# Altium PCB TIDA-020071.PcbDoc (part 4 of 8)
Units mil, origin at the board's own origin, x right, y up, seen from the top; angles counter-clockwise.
Board outline 5750 x 4050 mil, 6 copper layers (Top Layer, GND PLANE-1, SIGNAL LAYER, SIGNAL/POWER LAYER, GND PLANE-2, Bottom Layer), stack 59.616 mil thick; 776 components, 498 nets, 2205 pads, 871 vias.
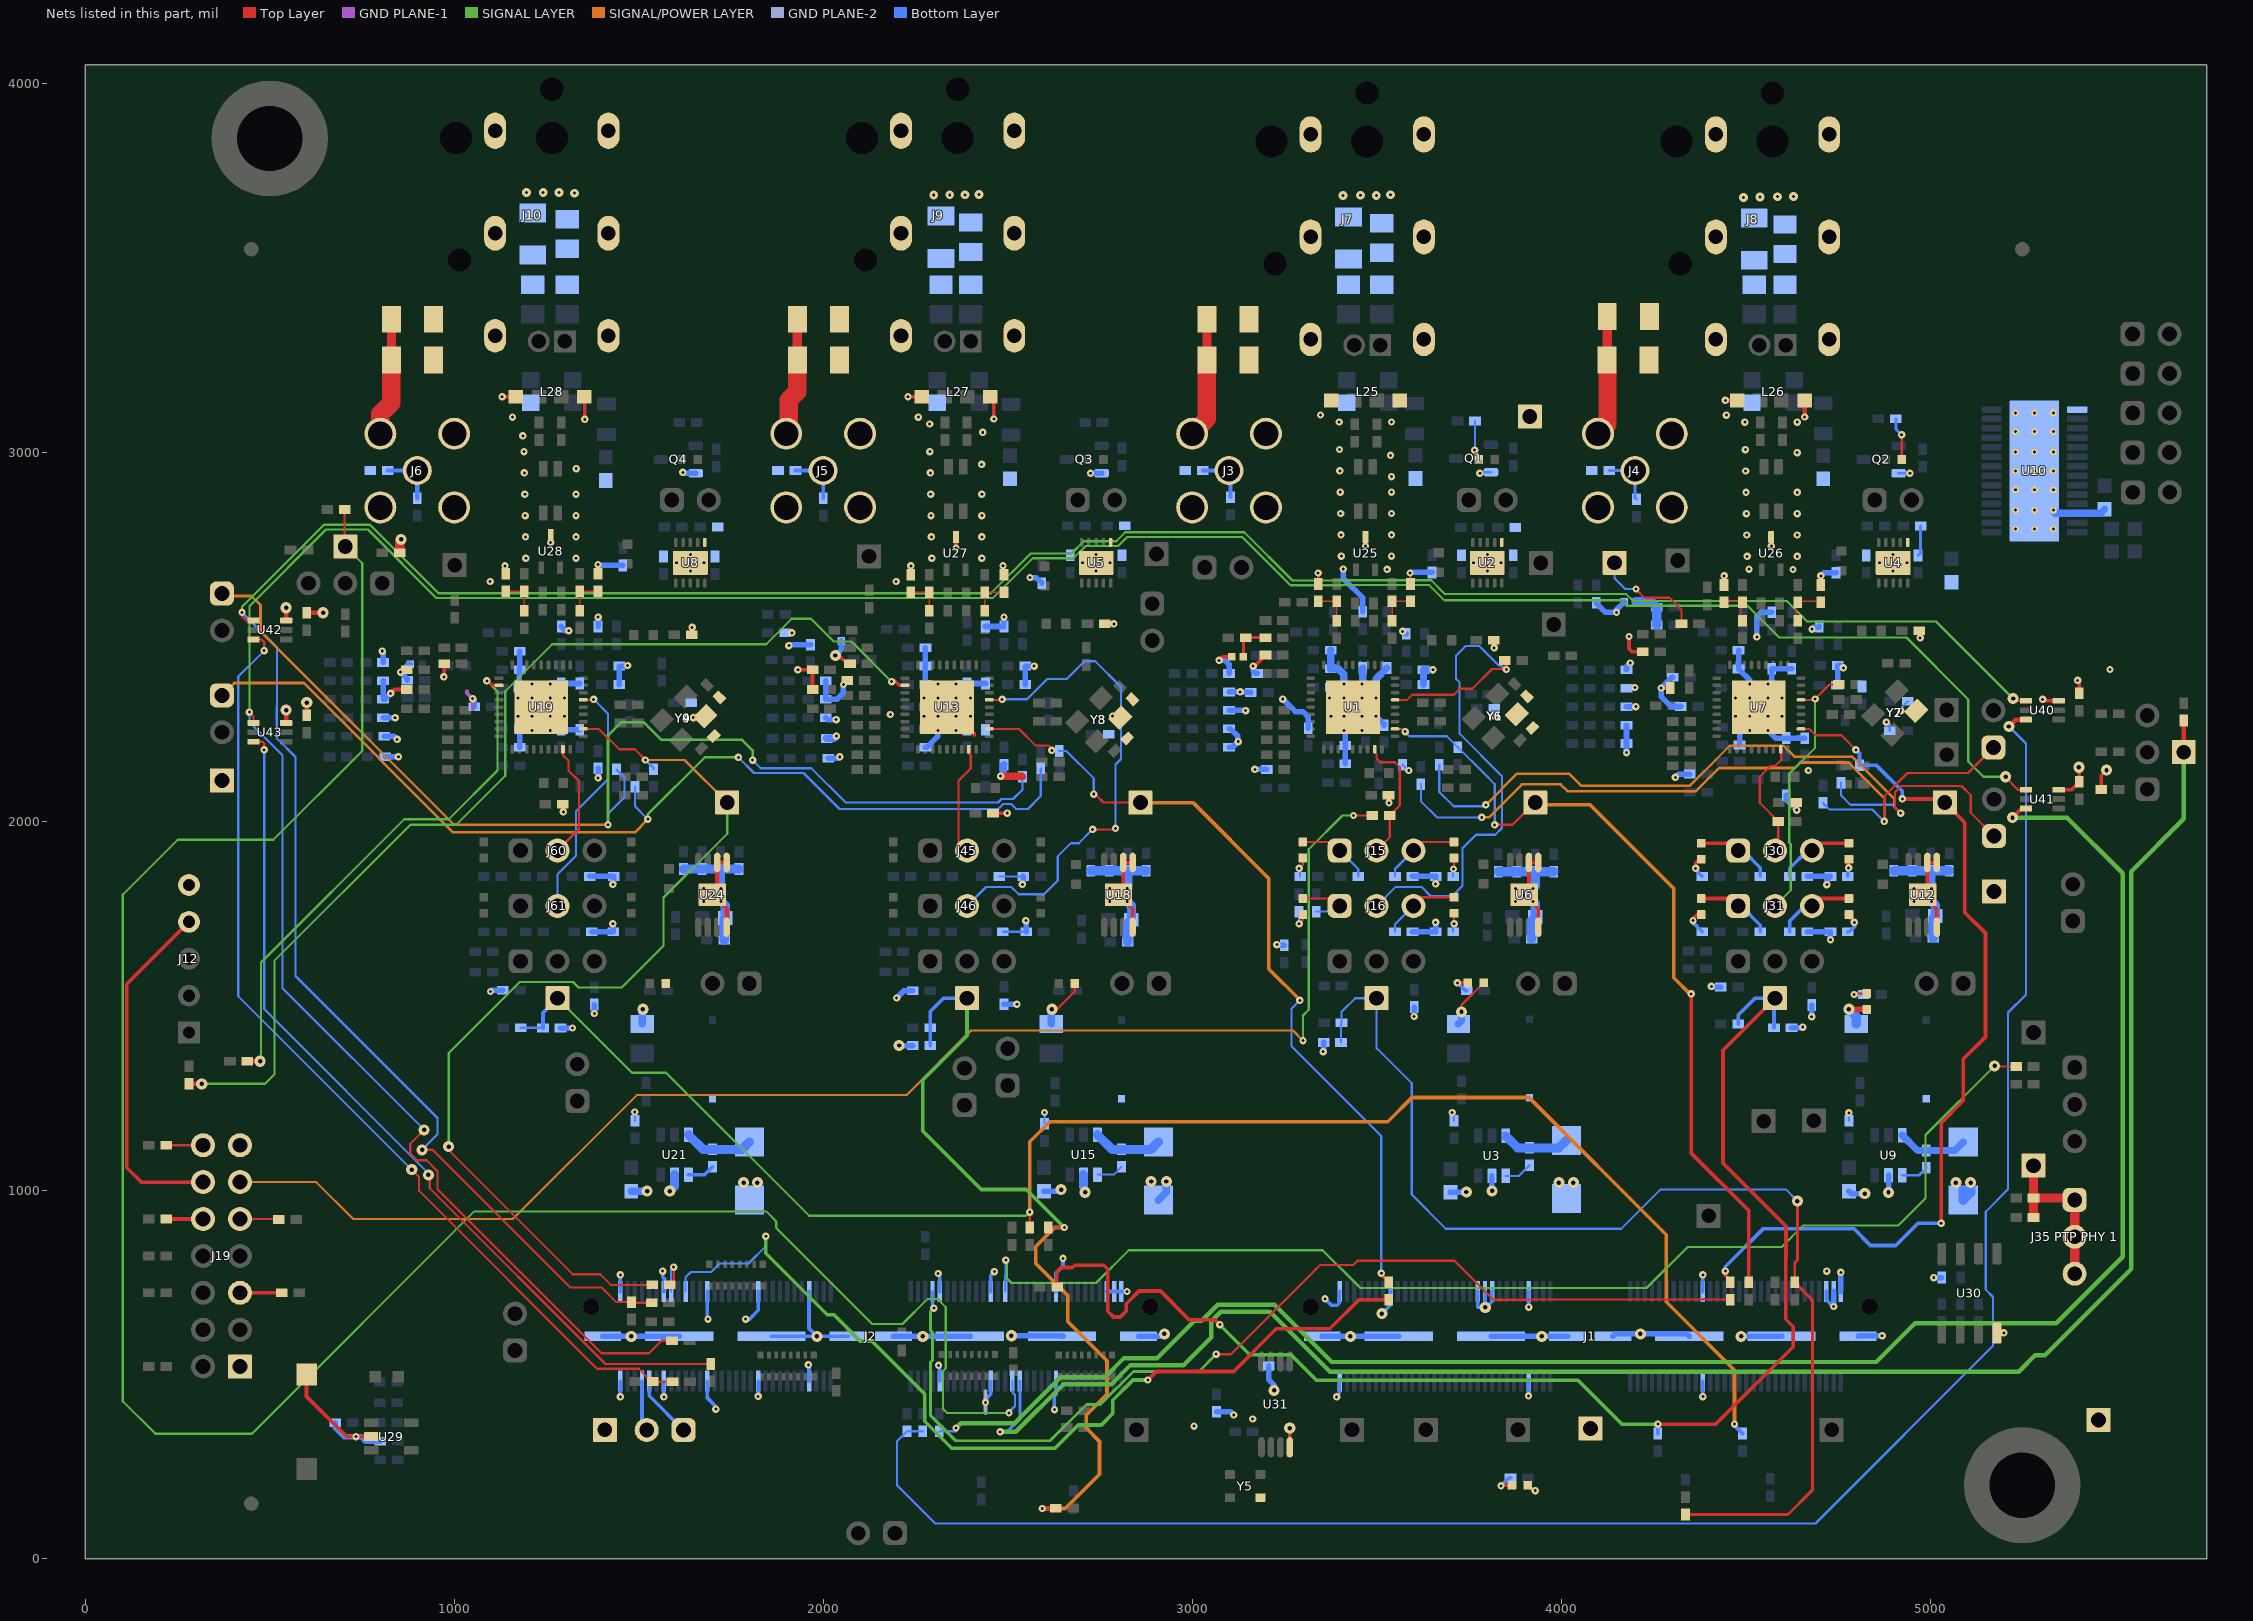
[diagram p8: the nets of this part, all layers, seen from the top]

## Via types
v1: diameter 20, hole 8, Top Layer to Bottom Layer, tented both sides, 637 vias
v2: diameter 30, hole 12, Top Layer to Bottom Layer, tented both sides, 105 vias
v3: diameter 19.68, hole 7.87, Top Layer to Bottom Layer, tented bottom, 68 vias
v4: diameter 19.68, hole 7.87, Top Layer to Bottom Layer, 25 vias
v5: diameter 24, hole 8, Top Layer to Bottom Layer, tented both sides, 24 vias
v6: diameter 19.68, hole 7.87, Top Layer to Bottom Layer, tented both sides, 12 vias

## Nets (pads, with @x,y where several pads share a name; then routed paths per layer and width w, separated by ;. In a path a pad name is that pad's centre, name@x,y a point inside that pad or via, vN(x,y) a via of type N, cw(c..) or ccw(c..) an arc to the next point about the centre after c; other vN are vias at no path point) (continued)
GND: C1.2 C2.2 C4.2 C5.2 C6.2 C7.2 C8.2 C9.2 C10.2 C11.2 C12.2 C13.2 C14.2 C15.2 C16.2 C17.2 C18.2 C19.2 C20.2 C21.2 C22.2 C23.2 C24.2 C25.2 C26.2 C27.2 C28.2 C29.2 C30.2 C31.2 C32.2 C33.2 C34.2 C35.2 C36.2 C38.2 C39.2 C40.2 C41.2 C42.2 C43.2 C44.2 C45.2 C46.2 C47.2 C48.2 C49.2 C50.2 C51.2 C52.2 C53.2 C54.2 C55.2 C56.2 C57.2 C58.2 C59.2 C60.2 C61.2 C62.2 C63.2 C64.2 C65.2 C66.2 C67.2 C68.2 C69.2 C70.2 C72.2 C73.2 C74.2 C75.2 C76.2 C77.2 C78.2 C79.2 C80.2 C81.2 C82.2 C83.2 C84.2 C85.2 C86.2 C87.2 C88.2 C89.2 C90.2 C91.2 C92.2 C93.2 C94.2 C95.2 C96.2 C97.2 C98.2 C99.2 C100.2 C101.2 C102.2 C103.2 C104.2 C106.2 C107.2 C108.2 C109.2 C110.2 C111.2 C112.2 C113.2 C114.2 C115.2 C116.2 C117.2 C118.2 C119.2 C120.2 C121.2 C122.2 C123.2 C124.2 C125.2 C126.2 C127.2 C128.2 C129.2 C130.2 C131.2 C132.2 C133.2 C134.2 C135.2 C136.2 C139.1 C140.2 C143.2 C144.2 C145.2 C146.2 C147.2 C150.1 C151.2 C154.2 C155.1 C161.1 C162.2 C165.2 C166.2 C169.1 C170.2 C173.2 C174.2 C175.2 C176.1 C177.2 C178.2 C200.1 C201.1 C202.1 C203.1 C314.2 C317.2 C320.2 C322.2 D1.2 D2.1 D3.1 D9.2 D11.1 D17.2 D19.1 D25.2 D27.1 D33.2 D34.1 D35.2 D36.1 D37.2 D38.1 D39.2 D40.1 GND.1 J1.1 J1.3 J1.5 J1.39 J1.40 J1.67 J1.68 J1.77 J1.79 J1.81 J1.105 J1.119 J1.120 J1.A1 J1.A2 J1.A3 J1.A4 J1.A5 J1.A6 J1.A7 J1.A8 J2.1 J2.3 J2.5 J2.19 J2.20 J2.37 J2.38 J2.51 J2.52 J2.67 J2.68 J2.81 J2.82 J2.95 J2.96 J2.107 J2.108 J2.119 J2.120 J2.A1 J2.A2 J2.A3 J2.A4 J2.A5 J2.A6 J2.A7 J2.A8 J3.2 J3.3 J3.4 J3.5 J4.2 J4.3 J4.4 J4.5 J5.2 J5.3 J5.4 J5.5 J6.2 J6.3 J6.4 J6.5 J12.5 J19.1 J19.13 L25.3 L26.3 L27.3 L28.3 Q1.2 Q2.2 Q3.2 Q4.2 R12.1 R14.1 R17.2 R18.2 R21.2 R22.2 R23-1.1 R23-2.2 R30.1 R32.1 R34.1 R36.1 R38.1 R65.1 R67.1 R70.2 R71.2 R74.2 R75.2 R76-1.1 R76-2.2 R77.2 R83.1 R85.1 R87.1 R89.1 R91.1 R114.2 R118.1 R120.1 R123.2 R124.2 R127.2 R128.2 R129-1.1 R129-2.2 R130.2 R136.1 R138.1 R140.1 R142.1 R144.1 R151.2 R171.1 R173.1 R176.2 R177.2 R180.2 R181.2 R182-1.1 R182-2.2 R189.1 R191.1 R193.1 R195.1 R197.1 R227.1 R228.2 R230.1 R238.1 R239.2 R249.1 R250.2 R257.1 R258.2 R261.1 R275.1 R276.1 R277.1 R278.1 R279.1 R280.1 R281.1 R282.1 R307.2 R310.2 R340.2 R342.1 R344.1 R346.1 R348.2 R371.1 R373.1 R375.1 R379.1 R381.1 R383.1 R387.1 R389.1 R391.1 S1.2 U1.37 U2.6 U2.11 U3.2 U4.6 U4.11 U5.6 U5.11 U6.4 U6.5 U6.6 U6.9 U7.37 U8.6 U8.11 U9.2 U10.1 U10.12 U10.29@5282.83,2948.96 U12.4 U12.5 U12.6 U12.9 U13.37 U15.2 U18.4 U18.5 U18.6 U18.9 U19.37 U21.2 U24.4 U24.5 U24.6 U24.9 U25.3 U26.3 U27.3 U28.3 U29.2 U30.4 U31.4 U40.3 U41.3 U42.3 U43.3 Y1.2 Y2.2 Y3.2 Y4.2 Y5.2 Y6.2 Y7.2 Y8.2 Y9.2 | length 15952.3
  Top Layer w6: C169.1@1140,2670 v1@1140,2694.38 ; v1(1261.5,2755) U28.3@1261.51,2775 ; C170.2@1389.92,2670.34 v1(1389.92,2694.72) ; v2(2620,1490) 2633.77,1490 2681.8,1538.03 D19.1@2681.8,1560 ; C139.1@3341.73,2642.52 v1(3341.73,2672.21) ; v1(3590.48,2672.41) 3591.73,2671.15 C140.2@3591.73,2642.52 ; v2(3730,1482.88) 3730,1501.65 D3.1@3790,1561.65 ; C150.1@4441.73,2637.4 C150.1@4441.73,2639.76 v1(4441.73,2664.53) ; C43.2@4637.24,2050 4637.24,2030.88 v1(4638.62,2029.5) ; C151.2@4703.94,2637.4 C151.2@4703.94,2639.76 v1(4703.94,2664.53) ; v1@4919.24,2299.33 v1(4920.06,2299.33) v1@4921.25,2299.33
  Top Layer w8: v1@4970.55,2499.41 v1(4973.27,2496.69)
  Top Layer w10: S1.2@600,500 600,440.28 708.52,331.76 v1(734.01,331.76) U29.2@775,331.76 ; v1(828.03,2346.14) 838.54,2356.65 R281.1@871.38,2356.65 ; v1(972.11,2390.6) 972.76,2391.25 R282.1@972.76,2426.06 ; v1(1130,3150) D39.2@1167.01,3150 ; C111.2@1294.41,2045.2 1294.41,2026.08 v1(1295.79,2024.7) ; D40.1@1352.99,3150 1353.92,3149.07 v1(1353.92,3088.9) ; C110.2@1643.44,2504.62 1643.44,2523.74 v1(1644.82,2525.12) ; v1(1931.4,2410) R279.1@1971.38,2410 R383.1@1971.38,2356.65 ; v2(2032.93,2448.66) 2042.5,2448.66 2065.1,2426.06 R280.1@2072.76,2426.06 ; v1(2055,2370) 2065.31,2380.31 R381.1@2065.31,2384.47 ; v1(2230,3150) D37.2@2267.01,3150 ; v1(2360,2740) U27.3@2360,2770 ; 2409.36,2232.61 2409.36,2237.17 ; D38.1@2452.99,3150 2462.59,3140.4 v1(2462.59,3089.71) ; C77.2@2460.2,2021.5 v1(2498.91,2021.5) ; C76.2@2763.57,2534.62 v1(2787.95,2534.62) ; U18.4@2838.86,1712.4 2838.86,1761.61 v3(2800.47,1800) 2813.27,1812.79 U18.6@2813.27,1887.6 U18.5@2838.86,1887.6 ; v1(3073.31,2435.47) 3082.83,2445 C314.2@3107.26,2445 ; v1(3165.53,2419.81) 3168.73,2419.81 R346.1@3198.8,2449.88 ; v2(3264.65,354.76) 3264.79,354.62 U31.4@3264.79,302.7 ; v2@3513.76,665.01 v2(3514.4,665.01) ; C9.2@3532.37,2070 3532.37,2050.88 v1(3533.74,2049.5) ; C8.2@3817.24,2490 3817.24,2470.88 v1(3818.62,2469.5) ; D2.1@3910,200 3924.89,185.11 v1(3930,185.11) ; U6.4@3938.39,1712.4 3938.39,1761.61 v3(3900,1800) 3912.8,1812.79 U6.6@3912.8,1887.6 U6.5@3938.39,1887.6 ; v1(4183.9,2500.2) 4183.9,2467 4192.2,2458.7 R375.1@4221.19,2458.7 ; v1(4271.26,2360.73) R373.1@4295.58,2360.73 ; U12.4@5018.39,1712.4 5018.39,1761.61 v3(4980,1800) 4992.8,1812.79 U12.6@4992.8,1887.6 U12.5@5018.39,1887.6 ; U30.4@5181.5,612.76 v1(5200,612.76) ; v1(5305,2330) 5308.99,2326.01 U40.3@5348.69,2326.01 ; U41.3@5348.69,2085.08 5383.33,2085.08 C201.1@5404.4,2106.15 5404.4,2144.61 v2(5403.28,2145.72) ; v1(5400,2381.21) 5404.4,2376.82 C200.1@5404.4,2346.55 ; R307.2@5464.24,2085.38 5464.24,2124.14 v2(5478.1,2138)
  Top Layer w12: v2(544.4,2300.6) 544.4,2266.43 U43.3@544.74,2266.09 ; U42.3@544.74,2543.49 v2(544.74,2578.04) ; C203.1@600.45,2286.63 v2(600.45,2321.19) ; C202.1@600.45,2564.56 v2(645,2564.56) ; U24.4@1738.39,1712.4 1738.39,1761.61 v3(1700,1800) 1712.8,1812.79 U24.6@1712.8,1887.6 U24.5@1738.39,1887.6 ; v1(4445.31,3140) D35.2@4477.01,3140 ; D36.1@4660,3140 4660.29,3139.71 v1(4660.29,3094.94)
  Top Layer w15: v2(4780,1490) 4780.65,1489.35 D11.1@4828.3,1489.35
  Top Layer w20: v1(1647.95,2280.31) 1649.32,2281.69 1677.19,2281.69 Y4.2@1679.97,2284.47 ; v1(2481.21,2121.76) 2538.24,2121.76 2540,2120
  Top Layer w25: C174.2@830,3250 R258.2@830,3360 ; R310.2@852.24,2727.33 852.24,2759.42 v2(856.02,2763.2) ; C166.2@1930,3250 R250.2@1930,3360 ; C144.2@3040,3250 R228.2@3040,3360 ; C155.1@4124.33,3250 4124.97,3250.64 R239.2@4124.97,3367.29
  Top Layer w50: J6.2@800,3050 800,3103.77 830,3133.77 C174.2@830,3250 ; J5.2@1900,3050 1907.01,3057.01 1907.01,3141.01 1930,3164.01 C166.2@1930,3250 ; J3.2@3004.5,3050 J3.2@3000,3050 3040,3090 C144.2@3040,3250 ; J4.2@4100,3050 4125.83,3075.83 C155.1@4125.83,3250
  GND PLANE-1 w10: 1035,2351.19 1035,2346.65 v1(1050,2331.65) 1050,2302.88
  GND PLANE-2 w10: 2440,395.8 v1(2440,424.7) 2440,454.32
  Bottom Layer w6: v1(1489.37,1211.33) 1489.37,1207.4 1490,1206.77 R171.1@1490,1187.24 ; R124.2@2477.24,1850 R123.2@2542.76,1850 ; R128.2@2487.24,1700 R127.2@2550,1700 ; R118.1@2600,1180 2600,1199.26 2600.74,1200 2600.74,1209.26 v1(2600,1210) ; C24.2@3570,2152.76 3585.59,2137.16 v1(3587.06,2137.16) ; v1(3704.65,1210) 3710,1204.65 R12.1@3710,1187.24 ; v1(3780,2942.6) 3782.6,2945.2 Q1.2@3810,2945.2 ; R65.1@4780,1187.24 v1(4780,1209.13) ; v1(4881.61,2268.27) 4881.61,2272.15 4890.87,2262.9 C66.2@4890.87,2245 ; v1(4920.06,2299.33) 4919.62,2299.77 v1@4917.63,2299.77 ; C67.2@4939.49,2324.36 4917.63,2302.5 v1@4917.63,2299.77 ; v1@4917.63,2299.77 4917.63,2298 4915.87,2299.77 v1@4917.63,2299.77
  Bottom Layer w8: Q2.2@4914.49,2942.6 v1(4945.28,2942.6) ; C39.2@4967.32,2719.76 4974.57,2727.01 R67.1@4974.57,2799.76
  Bottom Layer w10: J2.120@1450,482.01 1450,439.46 v1(1450.2,439.27) ; J2.119@1450,725 1450.2,725.2 v1(1450.2,770) ; v1(1565,780) 1565,763.72 1570,758.72 1569.79,758.51 1569.79,726.68 J2.107@1568.11,725 ; J2.108@1568.11,482.01 1568.11,439.62 v1(1568.46,439.27) ; J2.96@1686.22,482.01 1686.22,436.26 1709.19,413.29 v1(1709.19,406.1) ; J2.95@1686.22,725 1686.22,651.78 v1(1688,650) ; v1(1790,650) 1800.19,650 1824.02,673.83 J2.81@1824.02,725 ; v1(1824.02,440.72) J2.82@1824.02,482.01 ; J2.A6@1860.24,603.5 v2(1983.05,603.5) ; v1(1960,526.31) 1960,526.73 1961.81,524.92 J2.68@1961.81,482.01 ; J2.67@1961.81,725 1961.81,624.74 v2(1983.05,603.5) ; J2.A5@2067.72,603.5 v2(1983.05,603.5) ; v1(2311.81,773.66) 2316.14,769.33 J2.51@2316.14,725 ; v1(2312.55,524.86) 2316.14,521.27 J2.52@2316.14,482.01 ; v1(2440,424.7) 2440,432.39 2453.94,446.33 J2.38@2453.94,482.01 ; J2.37@2453.94,725 2453.94,768.94 v1(2463.8,778.8) ; v1(2627,405) 2626.16,405.84 2626.16,441.54 2631.1,446.49 J2.20@2631.1,482.01 ; J2.19@2631.1,725 2631.1,775.33 2650,794.23 v1(2650,815) ; J2.5@2768.9,725 J2.3@2788.58,725 J2.1@2808.27,725 v1(2823.62,725) ; v1(3360,705) 3360.15,705 3377.75,687.4 3393.14,687.4 3399,693.25 3399,724 J1.119@3400,725 ; v1(3391.73,439.57) 3391.73,442.27 3399,449.54 3399,481 J1.120@3400,482.01 ; v2(3514.4,665.01) 3536.79,687.4 3536.79,724 J1.105@3537.8,725 ; J1.81@3774.02,725 3774.02,682.68 3774.26,682.44 v2@3794.06,682.44 ; J1.79@3793.7,725 3794.06,724.65 v2@3794.06,682.44 ; J1.77@3813.39,725 3812.38,724 3812.38,697.03 3797.8,682.44 v2@3794.06,682.44 ; v1(3911.81,442.18) J1.68@3911.81,482.01 ; J1.67@3911.81,725 3912.11,724.7 3912.11,682.97 v1(3912.4,682.68) ; v1(4384.25,440) J1.40@4384.25,482.01 ; J1.39@4384.25,725 v1(4384.25,770) ; J1.5@4718.9,725 4718.9,702.46 4737.15,684.21 v1(4738.58,684.21)
  Bottom Layer w15: R261.1@677.76,369.09 677.76,355.96 701.96,331.76 v1(734.01,331.76) 747.06,331.76 759.72,319.09 C175.2@800,319.09 ; v1(805,2460.47) 807.24,2458.23 R197.1@807.24,2430 ; R191.1@807.24,2280 v1(840,2280) ; R195.1@807.24,2380 R193.1@807.24,2330 811.89,2330 v1(828.03,2346.14) ; R189.1@810,2230 836.65,2230 v1(845.28,2221.38) ; R387.1@812.69,2174.29 v1(848.79,2174.29) ; R389.1@872.95,2381.86 872.95,2385.56 v1(855,2403.51) 876.48,2425 C322.2@881.5,2425 ; v1(1050,2331.65) 1054.38,2327.28 C125.2@1054.38,2310 ; v1(1098.37,1538) 1101.96,1541.59 R182-1.1@1131.62,1541.59 ; v3(1172.83,2284.13) 1177.24,2279.72 C120.2@1177.24,2250 ; v3(1172.83,2333.35) 1176.77,2337.28 C123.2@1176.77,2360 1176.77,2409.53 C118.2@1177.24,2410 C113.2@1177.24,2460 ; C115.2@1177.24,2200 C120.2@1177.24,2250 ; v3(1211.22,2245.75) 1210.32,2246.64 1180.6,2246.64 C120.2@1177.24,2250 ; v3(1260.43,2245.75) 1261.93,2247.24 C126.2@1290,2247.24 ; v3(1260.43,2371.73) 1261.46,2372.76 C124.2@1290,2372.76 C119.2@1340,2372.76 ; R278.1@1288,1439 v1(1320.71,1439) ; C114.2@1290,2527.24 1301.46,2515.78 v1(1310.5,2515.78) ; v3(1298.82,2284.13) 1298.82,2282.87 1294.31,2278.36 1294.31,2251.55 C126.2@1290,2247.24 ; C121.2@1340,2247.24 C126.2@1290,2247.24 ; R177.2@1367.24,1850 R176.2@1432.76,1850 1432.76,1831.1 v1(1430,1828.35) ; R181.2@1372.83,1700 R180.2@1431.38,1700 1431.38,1720.28 v1(1430,1721.65) ; v1(1380,1478.38) R182-2.2@1380,1502.76 ; v1(1389.92,2694.72) 1391.88,2692.76 C109.2@1456.51,2692.76 ; v1(1390,2117.16) C116.2@1390,2142.76 ; C112.2@1390,2527.24 v1(1390,2552.83) ; J2.A8@1402.76,603.5 v2(1480,603.5) J2.A7@1610.24,603.5 ; C122.2@1447.24,2370 C117.2@1447.24,2420 1468.38,2420 v1(1470,2421.62) ; v1(1620,2945.2) 1622.6,2942.6 Q4.2@1654.49,2942.6 ; v1(1907,2475.4) 1909.63,2478.03 R144.1@1965.79,2478.03 ; R138.1@2007.24,2280 2012.24,2275 v1(2035,2275) ; R142.1@2007.24,2380 R140.1@2007.24,2330 2036.85,2330 2055,2348.15 v1(2055,2370) ; R379.1@2013.62,2170.14 2041.2,2170.14 v1(2045,2173.94) ; v2(2032.93,2448.66) 2049.25,2464.98 C320.2@2049.25,2488 ; v1(2181.93,2288.74) 2181.93,2289.05 v1@2182.76,2289.88 ; J2.A4@2190.16,603.5 v2(2270,603.5) J2.A3@2397.64,603.5 J2.A3@2398.82,603.5 ; v1(2199.4,1520.4) 2219.05,1540 R129-1.1@2242.76,1540 ; v2(2205.98,1391.61) R277.1@2243.07,1391.61 ; v3(2272.83,2284.13) 2277.24,2288.54 C91.2@2277.24,2310 ; v3(2272.83,2333.35) 2277.24,2337.76 C89.2@2277.24,2370 C84.2@2277.24,2420 C79.2@2277.24,2470 ; C81.2@2277.24,2200 2281.18,2200 2310.32,2229.14 2310.32,2246.64 2280.6,2246.64 C86.2@2277.24,2250 ; v3(2360.43,2245.75) 2361.93,2247.24 C92.2@2390,2247.24 ; v3(2360.43,2371.73) 2361.46,2372.76 C90.2@2390,2372.76 C85.2@2440,2372.76 ; C80.2@2440,2527.24 C78.2@2490,2527.24 v1(2490,2552.83) ; R129-2.2@2490,1503.43 v1(2524.79,1503.43) ; v2(2510,605) 2646.14,605 J2.A2@2647.64,603.5 J2.A2@2650.14,603.5 ; v1(2540,1828.35) 2542.76,1831.1 R123.2@2542.76,1850 ; C88.2@2547.24,2370 C83.2@2547.24,2420 v1(2571.81,2420) v1@2572.83,2420 ; v1(2549.38,1730) 2550,1729.38 R127.2@2550,1700 ; v1(2560.5,2660) 2577.43,2660 C75.2@2592.54,2644.88 ; C70.2@2598.49,997.01 2641.37,997.01 v2(2645.2,1000.84) ; v1(2724.57,2942.6) Q3.2@2754.49,2942.6 ; J2.A1@2855.12,603.5 2918.5,603.5 v2(2925,610) ; C178.2@3066.15,399.47 3103.69,399.47 v1(3112.8,390.36) ; v1(3073.31,2435.47) 3089.23,2435.47 3100,2424.7 R38.1@3100,2400 ; R30.1@3100,2200 3109.69,2200 v1(3125,2215.31) 3124.05,2216.27 3124.05,2229.89 3103.94,2250 R32.1@3100,2250 ; R34.1@3100,2300 3100.33,2299.67 3144.67,2299.67 v1(3145,2299.33) ; R36.1@3100,2350 v1(3130,2350) 3130.94,2349.05 3158.43,2349.05 R340.2@3159.38,2348.11 ; v1(3165.53,2419.81) 3165.63,2419.71 3165.63,2406.81 3172.44,2400 R344.1@3176.38,2400 ; v1(3170,2140) R342.1@3202.76,2140 ; C177.2@3207.99,523.03 3207.99,485.36 3222.01,471.34 v2(3222.01,457) ; v1(3229.5,1664.88) 3230.88,1663.5 R23-1.1@3250,1663.5 ; v1(3245.67,2330.54) 3279.73,2296.48 3300.11,2296.48 3314.41,2282.19 C13.2@3314.41,2251.97 ; J1.A8@3352.76,603.5 v2(3428.89,603.5) J1.A7@3560.24,603.5 ; v1(3355,1375) 3356.38,1376.38 R275.1@3356.38,1400 ; v1(3409.55,2683.2) 3409.55,2657.91 3462.66,2604.8 C17.2@3462.66,2567.62 ; v3(3411.25,2245.77) 3415.35,2241.67 C18.2@3415.35,2205 C23.2@3415.35,2155 ; v3(3460.46,2284.16) 3470,2274.62 C14.2@3470,2260 ; v3(3498.84,2284.16) 3520,2263 C19.2@3520,2260 ; v1(3570.54,2514.33) 3577.62,2507.24 C20.2@3580,2507.24 ; v1(3590.48,2672.41) 3591.85,2673.78 C7.2@3650.35,2673.78 ; R22.2@3597.24,1700 R21.2@3660,1700 3660,1725.66 v1(3659.84,1725.66) ; R18.2@3597.24,1850 R17.2@3660,1850 v1(3660,1830) ; v1(3601.93,1470.29) R23-2.2@3601.93,1495.88 ; C2.2@3700,993.42 3743.93,993.42 3743.17,994.18 v2(3743.17,994.62) ; J1.A6@3810.24,603.5 v2(3947.55,603.5) J1.A5@4017.72,603.5 ; U3.2@3812.6,1038.37 3812.6,997.89 v2(3812.89,997.6) ; C34.2@4095,2591.38 4120.93,2565.45 v1(4150,2565.45) 4150,2572.6 C317.2@4171.65,2594.25 ; J1.A4@4140.16,603.5 4146.65,610 v2(4215,610) 4341.14,610 J1.A3@4347.64,603.5 ; v1(4177.24,2185.59) R83.1@4177.24,2210 R85.1@4177.24,2260 ; R87.1@4177.24,2310 v1(4202.83,2310) ; R91.1@4177.24,2410 4177.24,2418.19 v1(4187.4,2428.35) ; R348.2@4302.76,2390 4300.53,2390 v1(4271.26,2360.73) 4271.26,2337.29 4298.05,2310.5 C57.2@4324.38,2310.5 ; v1(4309.84,2118.35) 4318.88,2127.38 R371.1@4348.77,2127.38 ; v1@4407.17,1550 R76-1.1@4432.76,1550 ; v1@4407.2,1550.03 v1(4407.2,1552) ; v3(4472.86,2333.37) 4480.87,2341.38 C55.2@4480.87,2361.14 ; C45.2@4480.87,2463.2 C50.2@4480.87,2412.11 4511.25,2381.73 v3(4511.25,2371.76) ; C47.2@4483.62,2206.32 C52.2@4483.62,2254.14 4502.88,2254.14 v3(4511.25,2245.77) ; v2(4487.77,603.5) J1.A2@4597.64,603.5 ; v1(4530.63,2499.41) 4530.63,2554.91 4541.7,2565.98 C46.2@4571.23,2565.98 ; v3(4560.46,2245.77) 4581.23,2225 C58.2@4610,2225 4610.25,2224.75 C53.2@4660.55,2224.75 ; v3(4560.46,2371.76) 4571.23,2382.53 C56.2@4571.23,2412.9 C51.2@4625,2412.9 ; C48.2@4610,2070.12 4610,2058.12 v1(4638.62,2029.5) ; R276.1@4624.41,1440 4653.34,1440 v1(4655,1441.66) ; R75.2@4667.24,1700 R74.2@4730,1700 v1(4730,1678.35) ; R71.2@4667.24,1850 R70.2@4730,1850 4721.09,1841.09 4721.09,1828.35 v1(4720.3,1827.56) ; v1(4679.2,1469.67) R76-2.2@4679.2,1501.38 ; v1(4680,2520) 4685.27,2525.27 4700,2525.27 C44.2@4700,2527.24 ; v1(4703.94,2664.53) 4712.16,2672.76 C41.2@4745.13,2672.76 ; v1(4738.58,684.21) J1.3@4738.58,725 ; C54.2@4747.61,2367.79 4749.99,2370.18 C49.2@4749.99,2421.62 4758.38,2421.62 v1(4765,2415) ; J1.1@4758.27,725 v1(4758.27,776.74) ; C36.2@4780,997.01 4786.71,990.3 v2(4822.9,990.3) ; J1.A1@4805.12,603.5 4806.61,605 v1(4870,605) ; v2(4887.4,993.42) U9.2@4887.4,1040 ; v1(5010,762.76) C176.1@5031.5,762.76
  Bottom Layer w20: C104.2@1480,997.01 v2(1522.91,997.01) ; C106.2@1510,1450 1510,1488.62 v2(1511.38,1490) ; R136.1@2010,2224 2029.59,2224 v1(2035.59,2230) ; v1(2481.21,2121.76) 2488.19,2128.73 2488.19,2150.94 C82.2@2490,2152.76 ; C72.2@2618.49,1450 2618.49,1488.49 v2(2620,1490) ; D17.2@2908.49,972.52 2930,994.03 v2(2930,1023.11) ; v3(3372.86,2333.37) 3375.53,2336.04 C11.2@3375.53,2362.76 ; C21.2@3375.53,2462.76 C16.2@3375.53,2412.76 3396.24,2412.76 3411.25,2397.75 v3(3411.25,2371.76) ; v3(3460.46,2371.76) 3462.66,2373.96 C12.2@3462.66,2414.72 ; v3(3498.84,2333.37) 3498.84,2385.57 C22.2@3528,2414.72 ; C10.2@3627.24,2370 C15.2@3627.24,2410 v1(3652.83,2410) ; C4.2@3721.65,1450 3730,1458.35 v2(3730,1482.88) ; v6(5334.01,2842.66) 5334.01,2839.55 5339.76,2833.8 U10.12@5398.97,2833.8 5462.35,2833.8 5472.83,2844.28 R230.1@5472.83,2845.26
  Bottom Layer w25: v2(1584.34,997.01) 1597.4,1010.07 U21.2@1597.4,1041.73 ; C132.2@1621.79,1869.92 C131.2@1671.79,1869.92 C130.2@1721.79,1869.92 ; v3(1723.62,1782.28) 1734.78,1771.13 C128.2@1734.78,1737.16 1731.79,1734.17 C127.2@1731.79,1677.16 ; v3(1723.62,1817.72) 1721.79,1819.55 C130.2@1721.79,1869.92 ; C129.2@1771.79,1869.92 C130.2@1721.79,1869.92 ; 2705.89,1009.91 U15.2@2705.89,1041.73 ; C98.2@2725.51,1865.04 C97.2@2775.51,1865.04 C96.2@2825.51,1865.04 ; v3(2824.09,1782.28) 2835.51,1770.87 C94.2@2835.51,1732.28 2825.51,1722.28 C93.2@2825.51,1672.28 ; v3(2824.09,1817.72) 2825.51,1819.13 C96.2@2825.51,1865.04 ; C95.2@2875.51,1865.04 C96.2@2825.51,1865.04 ; C30.2@3830,1862.76 C29.2@3880,1862.76 C28.2@3930,1862.76 ; C25.2@3920,1680 3920,1730 C26.2@3930,1740 3930,1775.9 v3(3923.62,1782.28) ; v3(3923.62,1817.72) 3930,1824.09 C28.2@3930,1862.76 ; C27.2@3980,1862.76 C28.2@3930,1862.76 ; v2(4780,1490) 4800,1470 C38.2@4800,1450 ; C64.2@4901.61,1865.16 C63.2@4951.61,1865.16 C62.2@5001.61,1865.16 ; v3(5003.62,1782.28) 5014.61,1771.3 C60.2@5014.61,1742.4 5008.86,1736.65 C59.2@5008.86,1682.4 ; v3(5003.62,1817.72) 5001.61,1819.72 C62.2@5001.61,1865.16 ; C61.2@5051.61,1865.16 C62.2@5001.61,1865.16 ; D9.2@5090,1000 D9.2@5090,972.52 5110,992.52 v2(5110,1020)
  other v1: 3005,360 3163.91,379.52 4720,780 4670,2137.16 3819.98,2283.39 2784.65,2284.13 4200,2362 5487.7,2410.82 1915,2510 1097.63,2649.4 2197.63,2649.4 3528.63,2682.2 4628.43,2681.81 4509.35,2682.81 1137.64,2691.62 2237.64,2691.62 2487.56,2691.96 1194.4,2712.3 1330.2,2712.3 2294.4,2712.3 2430.2,2712.3 3404.4,2717.89 3540.2,2717.89 4504.2,2717.5 4640,2717.5 4569.8,2745.2 3470,2745.59 1193.4,2770.1 1330.2,2770.1 2293.4,2770.1 2430.2,2770.1 4503.2,2775.3 4640,2775.3 3403.4,2775.69 3540.2,2775.69 1192.4,2827.9 1330.2,2827.9 2292.4,2827.9 2430.2,2827.9 3402.4,2833.49 3540.2,2833.49 4502.2,2833.1 4640,2833.1 1191.4,2885.7 1330.2,2885.7 2291.4,2885.7 2430.2,2885.7 3401.4,2891.29 3540.2,2891.29 4501.2,2890.9 4640,2890.9 3540.2,2933.5 1190.4,2943.5 2290.4,2943.5 3400.4,2949.09 4500.2,2948.7 1330.81,2955.13 2429.61,2966.84 3537.66,2991.2 4639.84,2998.54 1189.4,3001.3 2289.4,3001.3 4499.2,3006.5 3399.4,3006.89 1186.07,3044.12 2432.59,3053.63 2288.4,3075.99 4498.2,3081.19 4640,3081.19 3398.4,3081.58 3540.2,3081.58 1157.93,3094.9 2257.93,3094.9 3347.93,3100.49 4447.73,3100.1
  other v2: 3794.41,682.09 2709.84,994.03 1784.65,1020 1821.63,1020 3993.87,1020 4033.27,1020 5070,1020 2888.73,1023.11
  other v3: 1676.38,1782.28 2776.85,1782.28 3876.38,1782.28 4956.38,1782.28 1676.38,1817.72 2776.85,1817.72 3876.38,1817.72 4956.38,1817.72 2311.22,2245.75 3460.46,2245.77 1211.22,2284.13 1260.43,2284.13 2311.22,2284.13 2360.43,2284.13 2398.82,2284.13 3376,2284 3411.25,2284.16 4472.86,2284.16 4511.25,2284.16 4560.46,2284.16 4598.85,2284.16 1211.22,2333.35 1260.43,2333.35 1298.82,2333.35 2311.22,2333.35 2360.43,2333.35 2398.82,2333.35 3411.25,2333.37 3460.46,2333.37 4511.25,2333.37 4560.46,2333.37 4598.85,2333.37 1211.22,2371.73 2311.22,2371.73
  other v4: 1640,2677.36 2740,2677.36 3800,2677.36 4900,2677.36 1602.6,2700 1677.4,2700 2702.6,2700 2777.4,2700 3762.6,2700 3837.4,2700 4862.6,2700 4937.4,2700 1640,2722.64 2740,2722.64 3800,2722.64 4900,2722.64 5231.65,2897.78 5282.83,2897.78 5334.01,2897.78 5231.65,2948.96 5282.83,2948.96 5334.01,2948.96 5231.65,3000.14 5282.83,3000.14 5334.01,3000.14
  other v5: 4494.03,3690.43 4538.63,3691.12 4586.34,3692.16 4629.55,3692.85 3409.14,3695.28 2299.75,3696.44 3456.25,3696.12 3499.12,3695.6 2343.17,3697.28 2383.99,3697.28 3537.41,3697.38 2422.77,3698.16 1326,3701.63 1284.34,3703.26 1195.86,3703.81 1241.33,3703.81
  other v6: 5231.65,2791.48 5282.83,2791.48 5334.01,2791.48 5231.65,2842.66 5282.83,2842.66 5231.65,3055.26 5282.83,3055.26 5334.01,3055.26 5231.65,3106.44 5282.83,3106.44 5334.01,3106.44
GND720-1: C144.1 J7.S1 J7.S2 J7.S3 J7.S4 J7.S5 J7.S6 R228.1
GND720-2: C155.2 J8.S1 J8.S2 J8.S3 J8.S4 J8.S5 J8.S6 R239.1
GND720-3: C166.1 J9.S1 J9.S2 J9.S3 J9.S4 J9.S5 J9.S6 R250.1
GND720-4: C174.1 J10.S1 J10.S2 J10.S3 J10.S4 J10.S5 J10.S6 R258.1
GPIO3-3-TP: J19.14 R412.2 | length 100.4
  Top Layer w6: R412.2@219.16,1121.45 J19.14@319.53,1121.45
GPIO3-4-TP: J19.10 R417.2 | length 100.4
  Top Layer w10: R417.2@219.16,921.45 J19.10@319.53,921.45
GPIO4-3-TP: J19.9 R411.2 | length 105.3
  Top Layer w6: J19.9@419.53,921.45 523.31,921.45 R411.2@524.41,920.35
GPIO4-4-TP: J19.5 R416.2 | length 113
  Top Layer w10: J19.5@419.53,721.45 R416.2@532.51,721.45
GPIO5_3: R410.1 U13.20 | length 2850
  Top Layer w10: v1(2185.53,2377.88) 2185.53,2378.78 2186.74,2380 v1@2188.37,2380 ; v1@2192.06,2379.07 2195.57,2379.07 2206.84,2367.79 U13.20@2221.65,2367.79
  Top Layer w12: R410.1@281.23,1287.76 v2(315.78,1287.76)
  SIGNAL LAYER w6: v2(315.78,1287.76) 487.15,1287.76 512.71,1313.31 512.71,1621.09 881.62,1990 1005.5,1990 1138.45,2122.95 1138.45,2351.83 1265.51,2478.89 1845.51,2478.89 1915.03,2548.41 1967.31,2548.41 2028.86,2486.85 2076.55,2486.85 v1(2185.53,2377.88)
GPIO5_4: R415.1 U19.20 | length 1452.4
  Top Layer w10: v1@1085.53,2381.21 1086.74,2380 v1(1088.37,2380) ; v1@1092.06,2379.07 1103.34,2367.79 U19.20@1121.65,2367.79
  Top Layer w12: R415.1@439.67,1348.93 v2(474.23,1348.93)
  SIGNAL LAYER w6: v2(474.23,1348.93) 476.41,1351.1 476.41,1616.81 864.6,2005 985.21,2005 1117.5,2137.29 1117.5,2350.87 v1(1088.37,2380)
GPIO_ICSSG_1/2: J2.30 J70_1.1 R309.2 | length 5125.3
  Top Layer w12: J70_1.1@5687.51,2186.63 R309.2@5687.51,2272.39
  SIGNAL LAYER w12: v1(2479.8,344.8) 2522.2,344.8 2650.5,473.1 2780.6,473.1 2833,525.5 2977.23,525.5 3052,600.27 3052,644.53 3077.47,670 3210.9,670 3373.4,507.5 5240.1,507.5 5284.6,552 5311.4,552 5545.8,786.4 5545.8,1864.25 5687.51,2005.96 J70_1.1@5687.51,2186.63
  Bottom Layer w8: v1(2479.8,344.8) 2498.4,344.8 2534,380.4 2534,480.68 J2.30@2532.68,482.01
GPIO_ICSSG_3/4: J2.32 J73_1.1 R313.2 | length 6105.7
  Top Layer w6: R313.2@703,2844.17 703,2746.38 J73_1.1@705,2744.38
  SIGNAL LAYER w6: J73_1.1@705,2744.38 750.59,2698.79 750.59,2189.99 509.91,1949.31 250.81,1949.31 102,1800.5 102,427.6 190.3,339.3 451.86,339.3 1054.68,942.12 1845.76,942.12 1873.13,914.74 1873.13,896.87 2133.33,636.67 2214.89,636.67 2283.22,705 2309.78,705 2332.55,682.22 2332.55,516.58 2325,509.03 2325,406.7 2335.7,396 v1(2503.7,396)
  Bottom Layer w6: v1(2503.7,396) 2503.7,398.24 2520,414.54 2520,444.28 2512.99,451.29 J2.32@2512.99,482.01
"I2C2 SCL": J2.112 J37.1 | length 171.3
  Bottom Layer w10: J2.112@1528.74,482.01 1528.74,442.34 J37.1@1621.82,349.26
"I2C2 SDA": J2.114 J37.2 | length 138
  Bottom Layer w10: J2.114@1509.06,482.01 1509.06,362.03 J37.2@1521.82,349.26
INH-1: INH-1.1 R3.1 R46.2 R275.2 R285.2 | length 3084
  Top Layer w8: R3.1@4337.29,120.51 4614.88,120.51 4681,186.63 4681,702.27 R285.2@4633.27,750 4633.27,802.76 4640.5,809.99 v2(4640.5,970)
  Bottom Layer w6: R275.2@3403.62,1400 3403.62,1451.72 R46.2@3405,1453.1 3405,1482.87 3442.12,1520 INH-1.1@3500,1520 3500,1384.33 3595,1289.33 3595,987.64 3687.64,895 4163.23,895 4270,1001.77 4608.73,1001.77 v2(4640.5,970)
INH-2: INH-2.1 R9.1 R99.2 R276.2 R286.2 | length 3774.6
  Top Layer w10: R286.2@2634.57,737.2 2632.73,739.04 2632.73,776.96 2645.62,789.85 2675.23,789.85 2681.76,796.38 2760.34,796.38 2771.21,785.51 2771.21,671.51 2771.38,671.51 2786.89,656 2805.27,656 2821.37,672.09 2821.37,691.63 2855.94,726.21 2914.06,726.21 2992.27,648 3062,648 v1(3075,635) ; v1(4262.29,365.59) 4419.19,365.59 4628.91,575.31 4628.91,629.6 4608.85,649.66 4608.85,816.53 4609.37,817.04 4609.37,902 4439,1072.37 4439,1379 INH-2.1@4580,1520
  SIGNAL LAYER w10: v1(3075,635) 3156.5,553.5 3267.8,553.5 3336.5,484.8 4045.13,484.8 4164.34,365.59 v1(4262.29,365.59)
  Bottom Layer w10: R9.1@4262.29,340 v1(4262.29,365.59) ; R99.2@4480,1450 4480,1474.26 4525.74,1520 INH-2.1@4580,1520 ; R276.2@4577.17,1440 INH-2.1@4577.17,1517.16
INH-3: INH-3.1 R45.1 R152.2 R277.2 R287.2 | length 2240.9
  Top Layer w6: R287.2@2610,898.3 v1(2653.76,898.3)
  Top Layer w12: v1@2594.42,137.61 R45.1@2630.49,137.61
  SIGNAL LAYER w10: INH-3.1@2390,1520 2390,1417.8 2270.1,1297.9 2270.1,1159.99 2428.76,1001.33 2550.73,1001.33 v1(2653.76,898.3)
  SIGNAL/POWER LAYER w10: v1(2593.82,137.01) 2656.22,137.01 2749.21,230 2749.21,318.39 2712.87,354.73 2712.87,390.08 2769.14,446.34 2769.14,537.28 2662.73,643.69 2662.73,714.47 2576.22,800.98 2576.22,846.6 2627.92,898.3 v1(2653.76,898.3)
  Bottom Layer w10: R277.2@2290.32,1391.61 2290.32,1439.68 R152.2@2290,1440 2290,1483.62 2326.38,1520 INH-3.1@2390,1520 INH-3.1@2407.24,1502.76
INH-4: INH-4.1 R62.1 R205.2 R278.2 R288.2 | length 4472.3
  Top Layer w6: R288.2@2560,898.3 v1(2560,939.96)
  SIGNAL LAYER w6: INH-4.1@1280,1520 1482.15,1317.85 1574.25,1317.85 1962.1,930 2550.04,930 v1(2560,939.96)
  SIGNAL/POWER LAYER w10: v1(2560,939.96) 2560,1130.7 2614.58,1185.28 3530.2,1185.28 3595.65,1250.72 3912.68,1250.72 4284.8,878.6 4284.8,697.1 4470.08,511.82 v1(4470.08,365.59)
  Bottom Layer w6: R205.2@1180,1440 1239.76,1440 R278.2@1240.76,1439
  Bottom Layer w10: R278.2@1240.76,1439 1240.76,1480.76 INH-4.1@1280,1520 ; v1(4470.08,365.59) 4470.08,361.65 R62.1@4491.73,340
INT_N1: INT-1.1 R5.2 R49.1 U1.2 | length 2211.5
  Top Layer w6: U1.2@3550,2249.68 3569.65,2249.68 v1(3577.17,2242.16) ; v1@3820,1994.14 v1(3820,1989.69) 3868.48,1989.69 3929.29,2050.5 3929.89,2049.89 INT-1.1@3930,2050
  Top Layer w10: v1(4352.36,1531.7) 4352.36,1100.49 4508.27,944.58 R5.2@4508.27,750
  SIGNAL/POWER LAYER w10: INT-1.1@3930,2050 3935.5,2044.5 4078.33,2044.5 4305.51,1817.32 4305.51,1575.51 4352.36,1528.66 v1(4352.36,1531.7)
  Bottom Layer w6: v1(3577.17,2242.16) 3589.33,2230 3690,2230 R49.1@3720,2200 3790,2130 3820,2100 v1(3820,1989.69)
INT_N2: INT-2.1 R6.2 R102.1 U7.2 | length 2458.2
  Top Layer w6: U7.2@4650,2249.68 4650.19,2249.5 4672.75,2249.5 4690,2232.25 4759.73,2232.25 v1(4798.81,2193.17)
  Top Layer w10: v1(4445,780) 4445,768.85 4458.27,755.58 R6.2@4458.27,750 ; v1(4925,2060) 5030,2060 INT-2.1@5040,2050 5094.2,1995.8 5094.2,1752.4 5150,1696.6 5150,1415 5090,1355 5090,1241.65 5030,1181.65 v1(5030,910)
  Bottom Layer w10: v1(4445,780) 4445,791.78 4548.6,895.38 4793.07,895.38 4838.76,849.69 4907.18,849.69 4967.49,910 v1(5030,910) ; v1(4798.81,2193.17) 4808.54,2183.43 R102.1@4808.54,2150.87 4854.75,2150.87 4925,2080.61 v1(4925,2060)
INT_N2_Con: J2.53 R6.1 | length 2790.4
  Top Layer w6: v1(3065,555) 3105.21,555 3331.63,781.42 3331.63,781.75 3345.69,795.81 3346.02,795.81 3347.08,796.88 3436.58,796.88 3448.08,808.38 3581.04,808.38 3581.1,808.44 3711.22,808.44 3816.9,702.76 3902.78,702.76 3903.7,703.68 4457.35,703.68 R6.1@4458.27,702.76
  SIGNAL LAYER w8: v1(2300,680) 2291.55,671.55 2291.55,618.72 2296,614.27 2296,538.01 2291.55,533.56 2291.55,388.45 2359.51,320.49 2614.99,320.49 2713.5,419 2751.27,419 2840.77,508.5 3018.5,508.5 v1(3065,555)
  Bottom Layer w8: J2.53@2296.46,725 2296.46,678.99 2297.46,680 v1(2300,680)
INT_N3: INT-3.1 R7.2 R155.1 U13.2 | length 2181.5
  Top Layer w6: U13.2@2450,2249.68 2531.02,2249.68 2576.3,2204.41 2611.52,2204.41 2620,2195.93 v1(2620,2191.66) ; v1(2733.41,2072.75) 2737.25,2072.75 2760,2050 INT-3.1@2860,2050
  Top Layer w10: v1(3512.77,774.38) 3512.77,770.5 R7.2@3533.27,750
  SIGNAL/POWER LAYER w10: INT-3.1@2860,2050 3002.1,2050 3207.5,1844.6 3207.5,1599.36 3292.76,1514.11 v1(3292,1514.11)
  Bottom Layer w6: R155.1@2640,2190 2659.07,2190 2733.41,2115.66 v1(2733.41,2072.75) ; v1(3292,1514.11) 3269.54,1491.65 3269.54,1389.58 3512.77,1146.36 v1(3512.77,774.38)
INT_N3_Con: J2.101 R7.1 | length 2502.2
  Top Layer w10: v1(2880,485) 2903.41,508.41 3112.63,508.41 3227.93,623.7 3373.2,623.7 3452.26,702.76 R7.1@3533.27,702.76
  SIGNAL LAYER w10: v1(1844.56,874.68) 1844.56,828.64 2011.4,661.79 2029.18,661.79 2100,590.97 2131.6,590.97 2275.55,447.02 2275.55,373.36 2348.54,300.38 2628.68,300.38 2691.3,363 2754.11,363 2785.2,394.09 2785.2,430.3 2839.9,485 v1(2880,485)
  Bottom Layer w6: J2.101@1627.17,725 1627.17,763.38 1641.65,777.86 1696.84,777.86 1720,801.02 1797.72,801.02 1844.56,847.86 v1(1844.56,874.68)
INT_N4: INT-4.1 R8.2 R208.1 U19.2 | length 2647.9
  Top Layer w6: v2(985.1,1117.74) 985.1,1107.55 1321.05,771.6 1395.75,771.6 1424.45,742.9 R8.2@1536.88,742.9 ; U19.2@1350,2249.68 1392.03,2249.68 1447.3,2194.41 1489.53,2194.41 v1(1518.35,2165.59)
  SIGNAL LAYER w6: v2(985.1,1117.74) 985.1,1371.3 1177.4,1563.6 1322.12,1563.6 1336.72,1549 1454,1549 1567.4,1662.4 1567.4,1792.7 1740,1965.3 INT-4.1@1740,2050
  SIGNAL/POWER LAYER w6: v1(1518.35,2165.59) 1624.41,2165.59 INT-4.1@1740,2050
  Bottom Layer w6: v1(1518.35,2165.59) 1540,2143.94 R208.1@1540,2140
INT_N4_Con: J2.105 R8.1 | length 122
  Top Layer w6: R8.1@1584.12,742.9 1595,753.78 v1(1595,791.18)
  Bottom Layer w6: J2.105@1587.8,725 1587.8,783.98 v1(1595,791.18)
"LATCH IN IEP0 ICSSG1": "J35 PTP PHY 1.1" "J35 PTP PHY 1.2" "J35 PTP PHY 1.3" "J35_1 PTP PHY 1.1" R350.2 R351.1 | length 453.7
  Top Layer w25: R351.1@5280.47,925.72 R350.2@5280.47,978.23 ; 5280.47,1065.99 R350.2@5280.47,978.23 ; 5391.85,773.23 5391.85,873.23 5391.85,973.23 5386.85,978.23 R350.2@5280.47,978.23
"LATCH IN IEP1 ICSSG1": J2.33 R352.1 | length 3307.2
  Top Layer w6: v2(5175,1336.46) 5176.8,1334.66 R352.1@5233.23,1334.66
  SIGNAL LAYER w6: v1(2495,810) 2498,807 2498,760.31 2510.46,747.85 2739.31,747.85 2828.46,837 3353.37,837 3456.17,734.2 4231.3,734.2 4342.35,845.25 4597.26,845.25 4656.18,904.17 4914.17,904.17 4987.57,977.57 4987.57,1149.03 v2(5175,1336.46)
  Bottom Layer w6: J2.33@2493.31,725 2493.31,767.48 2495,769.17 v1(2495,810)
LED0-1: J19.11 R330.2 | length 3880.7
  Top Layer w6: v1(3437.32,2015) R330.2@3488.61,2015
  SIGNAL LAYER w6: v1(3300.51,1404.94) 3300.51,1472.86 3316.21,1488.56 3316.21,1923.74 3407.47,2015 v1(3437.32,2015)
  SIGNAL/POWER LAYER w6: J19.11@419.53,1021.45 626.15,1021.45 726.15,921.45 1158.8,921.45 1494.59,1257.24 2225.91,1257.24 2400.8,1432.13 3273.32,1432.13 v1(3300.51,1404.94)
LED_0-1: J15.2 R330.1 U1.35 | length 351.9
  Top Layer w6: U1.35@3494.88,2194.57 3494.88,2185.91 3500,2180.79 3500,2169.53 3510,2159.53 3549.34,2159.53 3562.99,2145.87 3562.99,2042.14 R330.1@3535.85,2015 3535.85,1955.85 J15.2@3500,1920
LED_0-2: J30.2 R331.1 U7.35 | length 331
  Top Layer w6: J30.2@4580,1920 4588.61,1928.61 R331.1@4588.61,1998.96 4538.35,2049.22 4538.35,2120 4567.87,2149.53 4580.53,2149.53 4596.39,2165.39 4596.39,2193.06 U7.35@4594.88,2194.57
LED_0-3: J45.2 U13.35 | length 299.7
  Top Layer w6: J45.2@2390,1920 2367.14,1942.86 2367.14,2109.64 2399.91,2142.42 2399.91,2178.2 2394.88,2183.23 U13.35@2394.88,2194.57
LED_0-4: J60.2 U19.35 | length 316.7
  Top Layer w6: J60.2@1280,1920 1338.35,1978.35 1338.35,2108.28 1310,2136.63 1310,2163.55 1294.88,2178.67 U19.35@1294.88,2194.57
LED_1-1: J16.2 R332.1 U1.6 | length 1567
  Top Layer w6: U1.6@3550,2328.42 3582.75,2328.42 3596.9,2342.57 3709.81,2342.57 3725.61,2358.36 3759.53,2358.36 3812.98,2411.81 3850.73,2411.81 v1(3851.76,2410.77) ; R332.1@3843.75,2435.02 R332.1@3847.69,2435.02
  Top Layer w10: R332.1@3847.69,2435.02 3851.76,2430.94 v1(3851.76,2410.77)
  Bottom Layer w6: J16.2@3500,1770 3551.6,1821.6 3621.6,1821.6 3646.2,1797 3705.5,1797 3732.99,1824.49 3732.99,1865.95 ; 3732.96,1865.98 3732.96,1926.39 3769.57,1962.99 3821.58,1962.99 3840,1981.41 3840,2121.7 3725,2236.7 3725,2375.94 3715,2385.94 3715,2448.21 3741.44,2474.64 3777.95,2474.64 3831.24,2421.36 3837.39,2421.36 3847.97,2410.77 v1(3851.76,2410.77)
LED_1-2: J31.2 R367.1 U7.6 | length 728.9
  Top Layer w6: U7.6@4650,2328.42 4686.12,2328.42 v1(4688.49,2330.79) 4727.7,2370 R367.1@4752.75,2370
  SIGNAL LAYER w6: J31.2@4580,1770 4622.48,1812.48 4622.48,1937.6 4618.62,1941.45 4618.62,2128.82 4688.49,2198.69 v1(4688.49,2330.79)
LED_1-3: J46.2 U13.6 | length 1362.5
  Top Layer w6: U13.6@2450,2328.42 2483.43,2328.42 v1(2485,2330) ; v1(2730.27,1977.39) 2789.46,1977.39 v1(2792.46,1980.39)
  Bottom Layer w6: J46.2@2390,1770 2441.24,1821.24 2510.12,1821.24 2529.77,1801.59 2598.28,1801.59 2635.66,1838.97 2635.66,1904.23 2671.43,1940 2692.88,1940 v1(2730.27,1977.39) ; v1(2485,2330) 2552.65,2330 2607.65,2385 2660.19,2385 2708.17,2432.98 2737.51,2432.98 2807.2,2363.29 2807.2,2168.12 2792.46,2153.37 v1(2792.46,1980.39)
LED_1-4: J61.2 U19.6 | length 661.5
  Top Layer w6: U19.6@1350,2328.42 1376.43,2328.42 v1(1378,2330)
  Bottom Layer w6: J61.2@1280,1770 1280,1855.87 1330,1905.87 1330,2026.71 1416.95,2113.66 1416.95,2291.05 v1(1378,2330)
MC_Main: J12.4 J19.12 | length 959.3
  Top Layer w10: J12.4@281.23,1726.78 112.54,1558.08 112.54,1060.55 151.63,1021.45 J19.12@319.53,1021.45
MDC1/2: J72.1 R50.2 R103.2 | length 2162
  Top Layer w6: v1(4920.13,2021.5) 4905,2036.63 4905,2078.12 4921.88,2095 5085.17,2095 5110,2070.17 5110,2022.65 J72.1@5173.35,1959.31
  SIGNAL/POWER LAYER w7: v1(3795.96,2043.96) 3880.25,2128.25 4021.65,2128.25 4054.7,2095.2 4348.57,2095.2 4419.13,2165.76 4419.13,2166.15 4457.08,2204.1 4602.7,2204.1 4632.19,2174.61 4788.38,2174.61 4903.1,2059.89 4903.1,2038.53 v1(4920.13,2021.5)
  Bottom Layer w6: R50.2@3670,2152.76 3670,2078.69 3708.77,2039.92 3791.92,2039.92 v1(3795.96,2043.96) ; R103.2@4758.35,2103.62 4758.35,2069.63 4783.98,2044 4897.63,2044 v1(4920.13,2021.5)
MDC3/4: J75.1 R156.2 R209.2 | length 2754.7
  SIGNAL LAYER w7: v1(1525,2005) 1525,2018.68 1679.08,2172.76 v1(1770,2172.76)
  SIGNAL/POWER LAYER w7: J75.1@370.45,2340.5 404.04,2374.1 592.82,2374.1 997.42,1969.5 1489.5,1969.5 v1(1525,2005)
  Bottom Layer w6: R209.2@1490,2092.76 1490,2040 v1(1525,2005) ; v1(1770,2172.76) 1812.57,2130.19 1946.94,2130.19 2044.49,2032.64 2474.69,2032.64 2488.55,2046.5 2509.26,2046.5 2523.13,2032.64 2555,2032.64 2590,2067.64 R156.2@2590,2142.76
MDC_CPSW: R300.2 U41.4 U43.4 | length 8136.9
  Top Layer w6: v1(445,2295.05) 443.56,2295.05 456.15,2282.46 U43.4@456.15,2266.09 ; v2(918.62,1163.17) 881.2,1125.75 881.2,1099.3 899.8,1080.7 925.56,1080.7 955,1051.26 955,1001.93 1399.1,557.83 1527.83,557.83 1561.7,591.7 R300.2@1590.48,591.7 ; v2(5205,2120) 5205,2118.62 5238.55,2085.08 U41.4@5260.11,2085.08
  SIGNAL LAYER w6: v1(445,2295.05) 445,2582.33 652.67,2790 766.23,2790 952.03,2604.19 2459.66,2604.19 2567.77,2712.3 2678.19,2712.3 2711.48,2745.59 2799.68,2745.59 2824.09,2770 3006.8,2770 3135.63,2770 3266.42,2639.21 3407.55,2639.21 3407.74,2639.41 3642.74,2639.41 3683.65,2598.5 4162.8,2598.5 4177.79,2583.51 4505.19,2583.51 4591.46,2497.24 4936.16,2497.24 5103.7,2329.7 5103.7,2161.3 5145,2120 v2(5205,2120)
  Bottom Layer w6: v1(445,2295.05) 445,2268.05 535,2178.05 535,1546.79 v2(918.62,1163.17)
MDC_ICSSG_1/2: R302.1 U41.6 | length 4988.9
  Top Layer w12: v2(5223.35,2009.31) 5247.94,2033.9 U41.6@5260.11,2033.9
  SIGNAL LAYER w12: v1(2360,355) 2372.8,367.8 2518.33,367.8 2642.63,492.1 2763,492.1 2815.4,544.5 2905.6,544.5 3006.5,645.4 3026,645.4 3069.6,689 3223.4,689 3378.4,534 4854.34,534 4959.44,639.1 5342.2,639.1 5522.2,819.1 5522.2,1858.4 5371.29,2009.31 v2(5223.35,2009.31) v2@5221.3,2007.26
  Bottom Layer w6: R302.1@2315,346.38 2361.38,346.38 2360,347.76 v1(2360,355)
MDC_ICSSG_3/4: R304.1 U43.6 | length 2383
  Top Layer w6: U43.6@456.15,2214.91 480.59,2214.91 485,2210.5 v1(485,2193.17) ; v2(930,1040.91) 933.91,1040.91 933.91,1004.64 1409.92,528.62 R304.1@1695,528.62
  Bottom Layer w6: v1(485,2193.17) 485,1490.64 930,1045.64 v2(930,1040.91)
MDIO1/2: J71.1 R51.2 R104.2 | length 2105.5
  Top Layer w6: v1(4875.76,1998.96) 4875.76,2067.27 4939,2130.5 5102.87,2130.5 J71.1@5171.67,2199.31
  SIGNAL/POWER LAYER w7: v1(3784.93,2010) 3804.14,2010 3893.84,2099.7 3998.5,2099.7 4017,2081.2 4365.27,2081.2 4427.87,2143.8 4633.6,2143.8 4648.5,2158.7 4778.9,2158.7 4875.76,2061.83 v1(4875.76,1998.96)
  Bottom Layer w6: R51.2@3620,2100 3620,2053.8 3663.8,2010 v1(3784.93,2010) ; R104.2@4710,2049.13 4728.13,2031 4843.72,2031 v1(4875.76,1998.96)
MDIO3/4: J74.1 R157.2 R210.2 | length 3060.9
  SIGNAL LAYER w7: v1(1416.95,1990) 1416.95,2232.25 1452.9,2268.2 1513.5,2268.2 1561.4,2220.3 1780.2,2220.3 1808.85,2191.65 v1(1808.85,2165)
  SIGNAL/POWER LAYER w7: J74.1@370.45,2616.63 377.08,2610 450,2610 475,2585 475,2514.11 999.11,1990 v1(1416.95,1990)
  Bottom Layer w6: v1(1416.95,1990) 1416.95,2019.79 1461.81,2064.65 1461.81,2118.19 R210.2@1440,2140 ; v1(1808.85,2165) 1830.66,2143.19 1967.99,2143.19 2061.18,2050 2473.67,2050 2483.17,2059.5 2514.5,2059.5 2540,2085 R157.2@2540,2120
MDIO_CPSW: R268.1 R301.2 U40.4 U42.4 | length 7811.5
  Top Layer w6: v1(425,2565.45) 425,2555 436.51,2543.49 U42.4@456.15,2543.49 ; v2(912.99,1109) 941,1109 1313.81,736.19 1399.33,736.19 1439.34,696.18 R268.1@1480.68,696.18 1482.36,694.49 R301.2@1535,694.49 ; v2(5225,2332.11) 5231.1,2326.01 U40.4@5260.11,2326.01
  SIGNAL LAYER w6: v1(425,2565.45) 425,2580.71 647.29,2803 771.61,2803 957.42,2617.19 2454.28,2617.19 2562.38,2725.3 2672.81,2725.3 2706.1,2758.59 2794.3,2758.59 2818.71,2783 3012.18,2783 3141.02,2783 3271.8,2652.21 3402.16,2652.21 3402.36,2652.41 3648.13,2652.41 3685.54,2615 4176.81,2615 4195.3,2596.51 4611.38,2596.51 4666.99,2540.9 5016.22,2540.9 v2(5225,2332.11)
  Bottom Layer w6: v1(425,2565.45) 520,2470.45 520,2311.55 519.4,2310.95 519.4,2224.15 570,2173.55 570,1580 955,1195 955,1151.01 v2(912.99,1109)
MDIO_ICSSG_1/2: R303.1 R306.2 U40.6 | length 5218.5
  Top Layer w12: v2(5213.82,2256.28) 5232.37,2274.83 U40.6@5260.11,2274.83
  Bottom Layer w6: R303.1@2270,346.38 R306.2@2227.24,346.38 2200,319.13 2200,200.07 2303.61,96.45 4689.41,96.45 5170.56,577.6 5170.56,710.19 5150.64,730.11 5150.64,940.98 5211.38,1001.73 5211.38,1480.85 5260.11,1529.57 5260.11,2209.99 v2(5213.82,2256.28)
MDIO_ICSSG_3/4: R305.1 R312.1 U42.6 | length 2652.3
  Top Layer w6: U42.6@456.15,2492.31 477.69,2492.31 485,2485 v1(485,2461.69) ; v2(885,1055.28) 905,1035.28 905,997.73 1387.11,515.62 1500,515.62 1534.34,481.28 R312.1@1538.62,481.28 1539.91,480 R305.1@1591.73,480
  Bottom Layer w6: v1(485,2461.69) 415,2391.69 415,1525.28 v2(885,1055.28)
NetC3_1: C3.1 D1.1 L5.1 U3.6 | length 186
  Bottom Layer w25: U3.6@3850,1146.64 3882.48,1114.16 C3.1@3914.25,1114.16 3993.87,1114.16 D1.1@4014.12,1134.41
NetC3_2: C3.2 U3.1 | length 76.1
  Bottom Layer w6: U3.1@3850,1038.37 3885.7,1038.37 C3.2@3914.25,1066.91
NetC31_1: C31.1 J3.1 R58.2 | length 145.2
  Bottom Layer w10: C31.1@3029.13,2950 J3.1@3100,2950 3104.13,2945.87 R58.2@3104.13,2877.36
NetC37_1: C37.1 D9.1 L6.1 U9.6 | length 191.6
  Bottom Layer w20: U9.6@4924.8,1148.27 4965.83,1107.24 C37.1@4990,1107.24 5067.24,1107.24 D9.1@5090,1130
NetC37_2: C37.2 U9.1 | length 73.5
  Bottom Layer w8: U9.1@4924.8,1040 4970,1040 C37.2@4990,1060
NetC65_1: C65.1 J4.1 R111.2 | length 148.8
  Bottom Layer w8: C65.1@4130.71,2950 J4.1@4200,2950 4200,2876.38 R111.2@4204.13,2872.24
NetC71_1: C71.1 D17.1 L7.1 U15.6 | length 190
  Bottom Layer w25: U15.6@2743.29,1150 2783.29,1110 C71.1@2808.49,1110 2888.49,1110 D17.1@2908.49,1130
NetC71_2: C71.2 U15.1 | length 73.9
  Bottom Layer w6: U15.1@2743.29,1041.73 2787.47,1041.73 C71.2@2808.49,1062.76
NetC99_1: C99.1 J5.1 R164.2 | length 150
  Bottom Layer w10: C99.1@1925,2950 J5.1@2000,2950 R164.2@2000,2875
NetC105_1: C105.1 D25.1 L8.1 U21.6 | length 190
  Bottom Layer w25: U21.6@1634.8,1150 1674.8,1110 C105.1@1700,1110 1780,1110 D25.1@1800,1130
NetC105_2: C105.2 U21.1 | length 73.9
  Bottom Layer w10: U21.1@1634.8,1041.73 1678.98,1041.73 C105.2@1700,1062.76
NetC133_1: C133.1 J6.1 R217.2 | length 155.3
  Bottom Layer w12: C133.1@819.68,2950 J6.1@900,2950 R217.2@900,2875
NetC137_1: C137.1 C139.2 R223.2 | length 102.8
  Top Layer w4: C139.2@3341.73,2595.28 R223.2@3391.73,2595.28 C137.1@3391.73,2542.52
NetC138_2: C138.2 C140.1 R224.1 | length 102.8
  Top Layer w4: C138.2@3541.73,2542.52 R224.1@3541.73,2595.28 C140.1@3591.73,2595.28
NetC143_1: C143.1 R225.1 R226.1 R227.2
NetC148_1: C148.1 C150.2 R234.2 | length 102.8
  Top Layer w4: C150.2@4437.32,2595.28 4487.32,2595.28 C148.1@4487.32,2542.52
NetC149_2: C149.2 C151.1 R235.1 | length 116.1
  Top Layer w4: C149.2@4637.32,2542.52 R235.1@4637.32,2595.27 ; R235.1@4641.73,2595.27 4701.18,2595.27 C151.1@4703.94,2592.52
NetC154_1: C154.1 R236.1 R237.1 R238.2
NetC159_1: C159.1 C161.2 R245.2 | length 102.8
  Top Layer w4: C161.2@2237.64,2620 R245.2@2287.64,2620 C159.1@2287.64,2567.24
NetC160_2: C160.2 C162.1 R246.1 | length 102.3
  Top Layer w4: C160.2@2437.64,2567.24 R246.1@2437.64,2620 C162.1@2487.22,2620
NetC165_1: C165.1 R247.1 R248.1 R249.2
NetC167_1: C167.1 C169.2 R253.2 | length 102.8
  Top Layer w4: C169.2@1140,2622.76 R253.2@1190,2622.76 C167.1@1190,2570
NetC168_1: C168.1 C170.1 R254.2 | length 102.8
  Top Layer w4: C168.1@1340,2570 R254.2@1340,2622.76 1389.58,2622.76 C170.1@1389.92,2623.1
NetC173_1: C173.1 R255.1 R256.1 R257.2
NetC314_1: C314.1 R314.1 R315.2 | length 108.4
  Top Layer w8: C314.1@3138.75,2445 3138.75,2490.83 R315.2@3144.93,2497.01 R314.1@3198.8,2497.01
NetC317_1: C317.1 R317.1 R318.2 | length 110.3
  Bottom Layer w25: C317.1@4203.15,2594.25 4244.73,2594.25 R318.2@4259.42,2579.57 R317.1@4259.42,2531.62
NetCLKOUT/GPIO_1: CLKOUT/GPIO.1 R408.2 | length 297.9
  Top Layer w6: v1(4202.9,2628.8) 4202.9,2627.5 4225.3,2605.1 4294.1,2605.1 4326.38,2572.82 R408.2@4326.38,2534.62
  Bottom Layer w6: CLKOUT/GPIO.1@4144.88,2700 4144.88,2657.8 4173.89,2628.8 v1(4202.9,2628.8)
NetD2_2: D2.2 R28.1 | length 64.8
  Top Layer w10: v1(3837.17,198.35) 3838.82,200 D2.2@3866.69,200
  Bottom Layer w10: v1(3837.17,198.35) 3858.82,220 R28.1@3862.76,220
NetD3_2: D3.2 R27.1 | length 62.3
  Top Layer w10: v1(3718.94,1561.65) D3.2@3746.69,1561.65
  Bottom Layer w10: v1(3718.94,1561.65) 3740.59,1540 R27.1@3744.53,1540
NetD4_1: D4.1 R25.2 | length 109
  Top Layer w6: v1(3765.59,3005.12) 3765.59,2991.1 D4.1@3776.69,2980
  Bottom Layer w6: v1(3765.59,3005.12) 3766.62,3006.15 R25.2@3766.62,3084
NetD5_1: D5.1 J15.1 R15.1 | length 200.4
  Top Layer w6: D5.1@3300,1943.31 3376.69,1943.31 J15.1@3400,1920
  Bottom Layer w6: J15.1@3400,1920 3450,1870 R15.1@3450,1850
NetD5_2: D5.2 R16.1 | length 55.3
  Top Layer w6: v1(3290,1871.65) 3300,1881.65 D5.2@3300,1900
  Bottom Layer w6: v1(3290,1871.65) 3292.76,1868.9 R16.1@3292.76,1850
NetD6_1: D6.1 R17.1 | length 51.1
  Top Layer w6: v1(3708.35,1870) 3710,1871.65 D6.1@3710,1900
  Bottom Layer w6: R17.1@3707.24,1850 3707.24,1868.9 v1(3708.35,1870)
NetD6_2: D6.2 J15.3 R18.1 | length 210.4
  Top Layer w6: J15.3@3600,1920 3623.31,1943.31 D6.2@3710,1943.31
  Bottom Layer w6: R18.1@3550,1850 3550,1870 J15.3@3600,1920
NetD7_1: D7.1 J16.1 R19.1 | length 178.2
  Top Layer w6: D7.1@3300,1790 3380,1790 J16.1@3400,1770
  Bottom Layer w6: R19.1@3336.54,1754.54 3384.54,1754.54 J16.1@3400,1770
NetD7_2: D7.2 R20.1 | length 66
  Top Layer w6: v1(3290,1721.65) 3300,1731.65 D7.2@3300,1746.69
  Bottom Layer w6: R20.1@3289.89,1754.54 3289.89,1721.76 v1(3290,1721.65) v1@3292.76,1718.9
NetD8_1: D8.1 R21.1 | length 51.1
  Top Layer w6: v1(3710,1721.65) D8.1@3710,1750
  Bottom Layer w6: R21.1@3707.24,1700 3707.24,1718.9 v1(3710,1721.65)
NetD8_2: D8.2 J16.3 R22.1 | length 210.4
  Top Layer w6: J16.3@3600,1770 3623.31,1793.31 D8.2@3710,1793.31
  Bottom Layer w6: R22.1@3550,1700 3550,1720 J16.3@3600,1770
NetD11_2: D11.2 R80.1 | length 60.6
  Top Layer w6: v1(4794.41,1530) 4797.06,1532.65 D11.2@4828.3,1532.65
  Bottom Layer w6: v1(4794.41,1530) R80.1@4820,1530
NetD12_1: D12.1 R78.2 | length 116.7
  Top Layer w8: v1(4923,3047) 4923,3044.24 4923.31,3043.94 D12.1@4923.31,2980
  Bottom Layer w8: R78.2@4907.24,3090 4907.24,3062.76 v1(4923,3047)
NetD13_1: D13.1 J30.1 R68.1 | length 210.8
  Top Layer w10: D13.1@4380,1940 4460,1940 J30.1@4480,1920
  Bottom Layer w10: J30.1@4480,1920 4493.11,1920 4540,1873.11 R68.1@4540,1850
NetD13_2: D13.2 R69.1 | length 64.8
  Top Layer w10: v1(4364.57,1871.65) 4364.57,1885.87 4375.39,1896.69 D13.2@4380,1896.69
  Bottom Layer w10: v1(4364.57,1871.65) 4362.83,1869.92 R69.1@4382.76,1850
NetD14_1: D14.1 R70.1 | length 47.8
  Top Layer w10: v1(4779.13,1873.11) 4779.13,1895.83 D14.1@4780,1896.69
  Bottom Layer w10: R70.1@4777.24,1850 4777.24,1871.22 v1(4779.13,1873.11)
NetD14_2: D14.2 J30.3 R71.1 | length 210.3
  Top Layer w10: J30.3@4680,1920 4700,1940 D14.2@4780,1940
  Bottom Layer w10: R71.1@4620,1850 4620,1872.28 4667.72,1920 J30.3@4680,1920
NetD15_1: D15.1 J31.1 R72.1 | length 207.7
  Top Layer w10: D15.1@4380,1790 4460,1790 J31.1@4480,1770
  Bottom Layer w10: J31.1@4480,1770 4487.8,1770 4540,1717.79 R72.1@4540,1700
NetD15_2: D15.2 R73.1 | length 75
  Top Layer w10: v1(4357.56,1730.24) 4357.56,1735.28 4368.98,1746.69 D15.2@4380,1746.69
  Bottom Layer w10: v1(4357.56,1730.24) 4355.04,1727.72 R73.1@4382.76,1700
NetD16_1: D16.1 R74.1 | length 62.6
  Top Layer w10: D16.1@4780,1746.69 4780,1740.66 v1(4795,1725.66)
  Bottom Layer w10: R74.1@4777.24,1700 4781.18,1700 4795,1713.81 v1(4795,1725.66)
NetD16_2: D16.2 J31.3 R75.1 | length 214.5
  Top Layer w10: J31.3@4680,1770 4700,1790 D16.2@4780,1790
  Bottom Layer w10: R75.1@4620,1700 4620,1729.45 4660.55,1770 J31.3@4680,1770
